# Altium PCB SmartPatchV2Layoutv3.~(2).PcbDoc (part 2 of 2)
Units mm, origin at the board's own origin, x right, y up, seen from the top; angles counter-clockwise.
Board outline 99.82 x 98.31 mm, 4 copper layers (Top Layer, Power, GroundPlane, Bottom Layer), stack 2.286 mm thick; 142 components, 77 nets, 387 pads, 123 vias.
Unrouted connection lines stored in the file: 2.
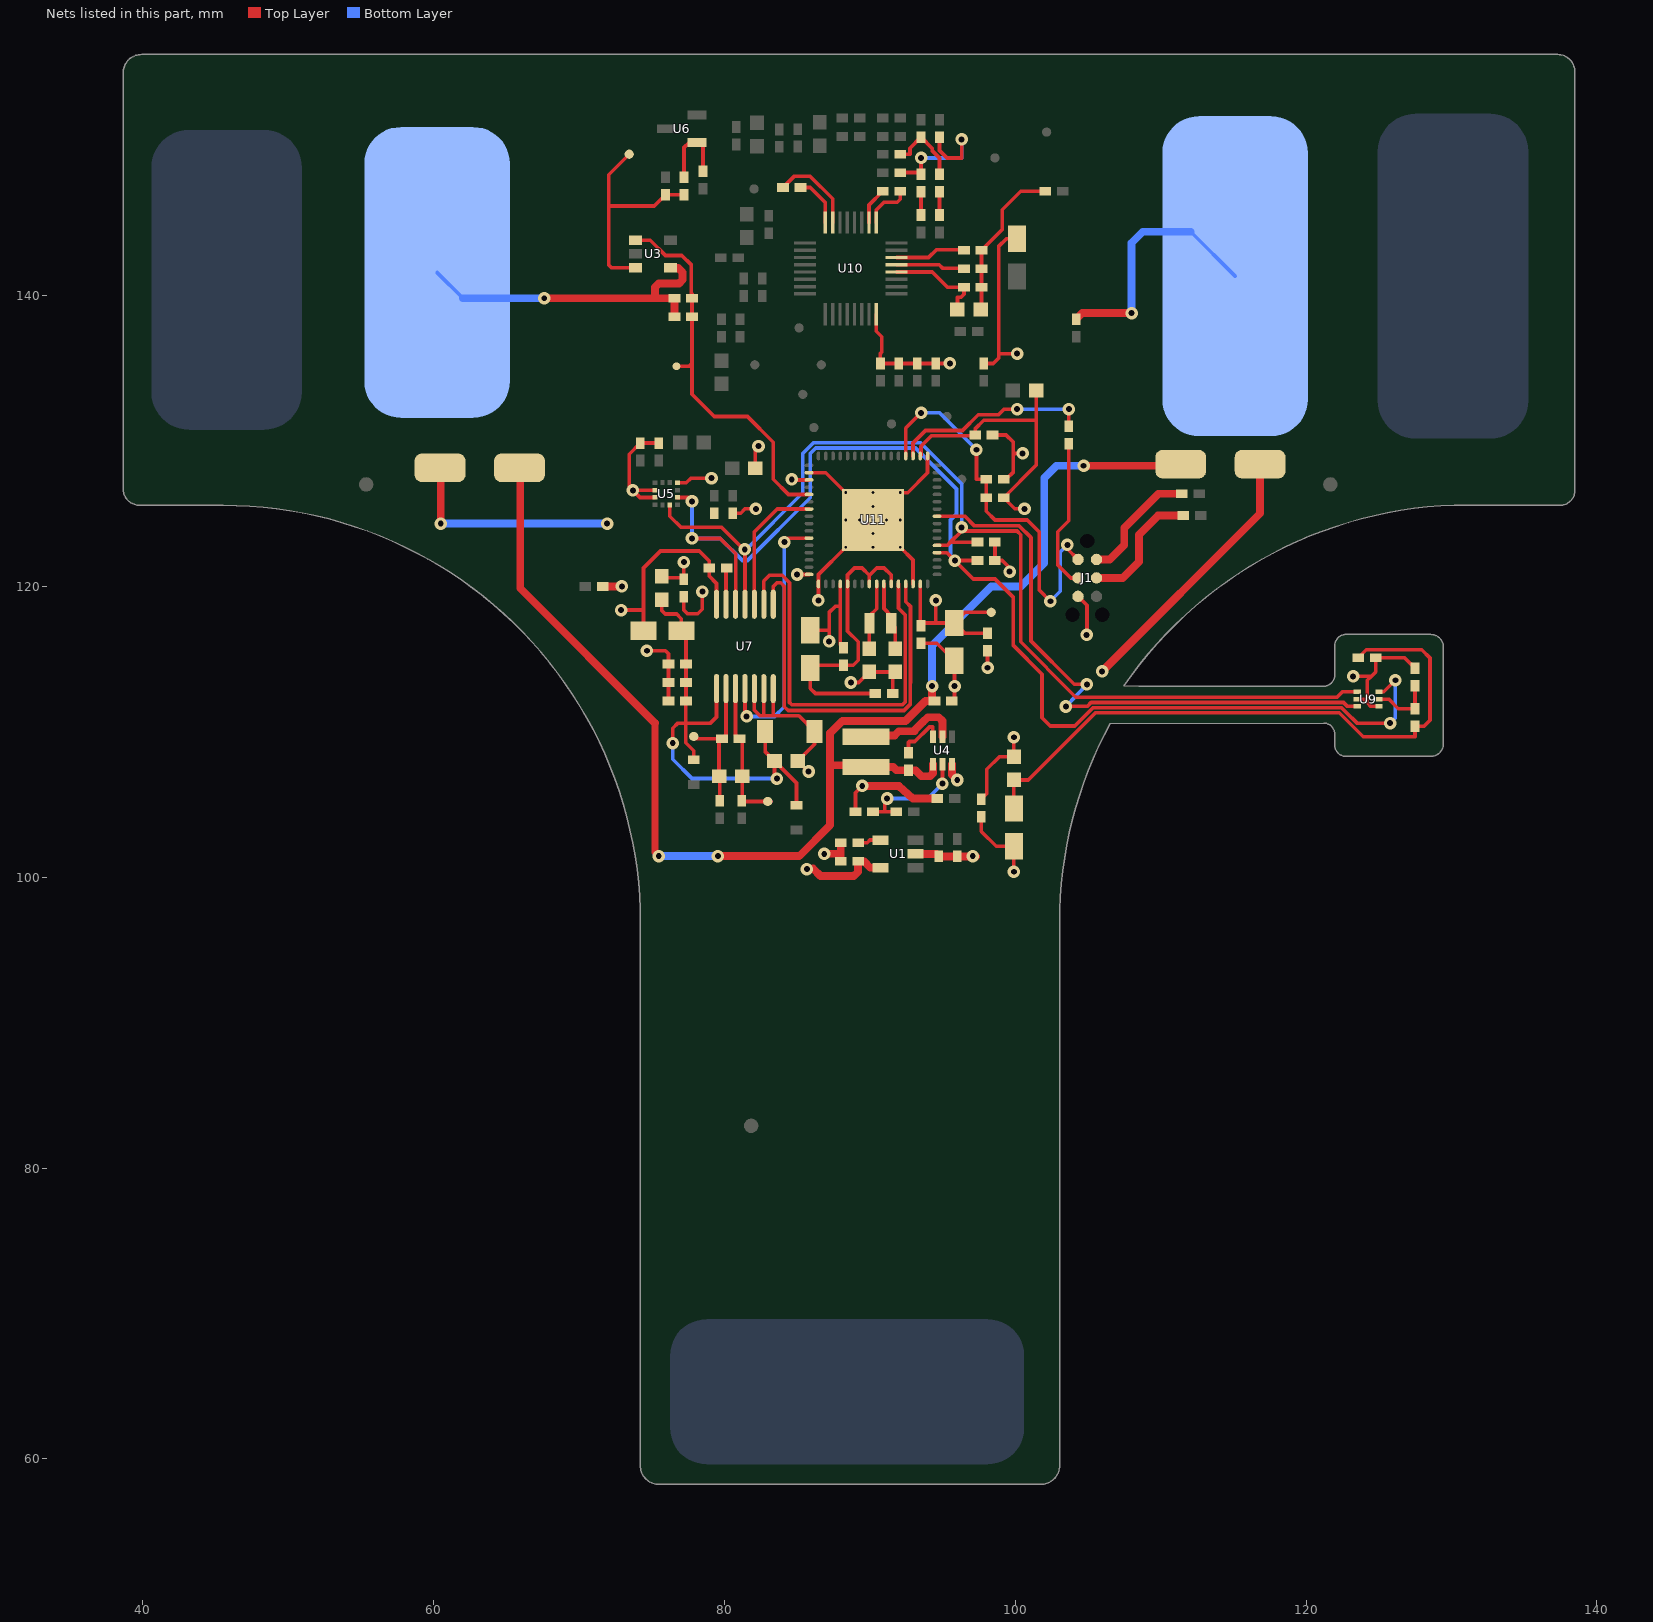
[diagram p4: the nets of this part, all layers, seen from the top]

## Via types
v1: diameter 0.864, hole 0.406, Top Layer to Bottom Layer, 110 vias
v2: diameter 0.5, hole 0.2, Top Layer to Bottom Layer, 13 vias

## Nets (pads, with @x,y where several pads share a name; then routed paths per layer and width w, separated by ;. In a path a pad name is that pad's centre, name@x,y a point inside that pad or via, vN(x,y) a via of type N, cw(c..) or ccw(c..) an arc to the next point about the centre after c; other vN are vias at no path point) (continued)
BOOST_INPUT: BT1.1 BT2.1 C43.1 L8.1 R13.1 U4.1 | length 94.4
  Top Layer w0.254: L8.1@89.739,107.681 L8.1@89.748,107.672 ; v1(94.285,113.132) v1@94.447,112.97
  Top Layer w0.5: 75.235,110.592 75.235,101.702 v1(75.489,101.448)
  Top Layer w0.54: BT1.1@65.964,127.991 65.964,119.863 75.235,110.592 ; v1(79.553,101.448) 85.141,101.448 87.274,103.581 87.274,109.906 88.113,110.744 92.456,110.744 93.828,112.116 C43.1@94.447,112.116 ; 87.274,107.696 L8.1@89.739,107.681 ; L8.1@89.738,107.57 91.616,107.57 91.837,107.35 92.283,107.35 ; R13.1@92.659,107.35 93.145,107.35 93.561,106.934 94.132,106.934 94.346,107.148 U4.1@94.346,107.762 ; C43.1@94.285,112.278 v1(94.285,113.132) ; v1(104.699,128.287) BT2.1@111.048,128.287
  Bottom Layer w0.54: v1(75.489,101.448) v1(79.553,101.448) ; v1(94.285,113.132) 94.285,115.926 98.349,119.99 100.381,119.99 101.997,121.606 101.997,127.448 102.836,128.287 v1(104.699,128.287)
DVCC: 6.1 C1.1 C4.1 C6.1 C10.1 C15.1 C26.1 L1.1 L2.1 L5.1 L7.1 R1.1 R6.2 R34.1 R35.1 U1.5 U11.18 U11.35 U11.48 U11.63 | length 52.8
  Top Layer w0.254: L1.1@75.489,120.59 77.067,120.59 C10.1@77.091,120.613 ; C10.1@77.216,120.488 v1(77.216,121.666) ; L5.1@82.131,128.118 82.131,129.426 v1(82.347,129.642) ; v1@84.677,127.312 U11.35@85.821,127.312 ; v1(85.003,120.812) U11.48@85.821,120.812 ; 89.982,100.65 90.038,100.65 ; U11.63@93.472,120.162 93.472,117.339 C6.1@93.523,117.288 ; U11.18@93.472,128.962 93.518,129.008 93.518,129.637 94.237,130.356 97.193,130.356 C26.1@97.241,130.404 97.241,130.82 97.841,131.42 101.397,131.42 ; C6.1@93.715,117.48 C1.1@95.809,117.48 ; 94.542,117.483 v1(94.542,119.027) ; C15.1@97.665,105.35 98.044,105.728 98.044,107.414 98.915,108.286 L2.1@99.906,108.286 v1(99.906,109.621) ; R1.1@98.095,116.78 96.509,116.78 C1.1@95.809,117.48 ; 6.1@98.349,118.212 96.541,118.212 C1.1@95.809,117.48 ; R35.1@98.603,123.038 R34.1@98.603,121.768 99.111,121.768 99.619,121.26 v1(99.619,121.006) ; v1(100.635,125.324) 99.965,125.324 R6.2@99.203,126.086 101.435,128.318 L7.1@101.435,133.452
  Top Layer w0.54: v1(85.674,100.559) v1@86.081,100.559 ; 86.106,100.584 86.614,100.076 88.9,100.076 89.2,100.376 C4.1@89.2,101.092 89.596,101.092 90.038,100.65 U1.5@90.748,100.65
  other v1: 84.633,127.356
EL_GSR1: 5.1 C34.2 R10.1 U3.4 | length 22.6
  Top Layer w0.254: U3.4@76.297,141.9 76.809,141.9
  Top Layer w0.54: v1(67.615,139.802) R10.1@76.575,139.802 C34.2@76.575,138.532 ; 75.235,139.852 75.235,140.564 75.489,140.818 76.875,140.818 77.129,141.072 77.129,141.58 76.809,141.9
  Bottom Layer w0.254: 5.1@60.249,141.58 5.1@62.027,139.802
  Bottom Layer w0.54: 5.1@62.027,139.802 v1(67.615,139.802)
EL_GSR2: 4.1 R9.2 | length 17.5
  Top Layer w0.54: R9.2@104.191,138.37 104.607,138.786 v1(108.001,138.786)
  Bottom Layer w0.254: 4.1@112.065,144.374 4.1@115.113,141.326
  Bottom Layer w0.54: v1(108.001,138.786) 108.001,143.612 108.763,144.374 4.1@112.065,144.374
GND: BT1.2 BT2.2 C1.2 C3.2 C4.2 C5.2 C6.2 C8.2 C9.2 C10.2 C11.2 C12.2 C14.2 C15.2 C19.2 C21.2 C22.2 C26.2 C27.2 C28.2 C29.2 C33.2 C36.2 C37.2 C38.1 C41.2 C42.2 C43.2 C44.2 C45.2 C46.2 C47.2 C50.2 C51.2 C69.2 C70.2 J1.6 R2.1 R3.1 R20.1 U1.2 U4.3 U5.4 U5.8 U5.9 U7.5 U7.6 U7.7 U7.14 U9.2 U9.4 U10.24 U11.17 U11.34 U11.49 U11.62 U11.65 | length 178.4
  Top Layer w0.254: v1(72.898,118.364) 74.443,118.364 ; C9.2@74.443,116.942 74.443,118.364 ; v1(74.676,115.57) 75.946,115.57 76.159,115.357 C36.2@76.159,114.656 C11.2@76.159,113.386 C37.2@76.159,112.116 ; U5.9@75.222,126.111 74.194,126.111 v1(73.711,126.594) ; U5.8@75.222,126.611 73.728,126.611 v1(73.711,126.594) ; C46.2@75.489,129.847 C21.2@74.219,129.847 73.457,129.085 73.457,126.848 v1(73.711,126.594) ; U5.4@76.772,127.111 77.376,127.111 77.698,127.433 v1(79.117,127.433) ; C10.2@77.216,119.288 77.216,118.364 77.47,118.11 78.174,118.11 78.486,118.422 v1(78.486,119.634) ; U7.14@79.464,118.764 79.464,120.193 78.953,120.704 C38.1@78.953,121.26 78.953,121.745 78.27,122.428 75.611,122.428 74.443,121.26 74.443,118.364 ; C22.2@80.569,125.024 81.124,125.024 81.424,125.324 v1(82.169,125.324) ; U7.5@82.064,112.964 82.064,111.484 82.448,111.1 83.363,111.1 ; 82.714,111.137 U7.6@82.714,112.964 ; U7.7@83.364,112.964 83.363,111.1 ; v1(85.797,107.266) 85.772,107.266 C42.2@85.047,107.991 86.201,109.145 C41.2@86.201,110.023 85.124,111.1 83.363,111.1 ; U11.34@85.821,127.812 86.971,127.812 v2(88.346,126.437) v2(90.221,124.562) ; v1(86.47,119.033) U11.49@86.47,120.162 86.47,120.811 v2(88.346,122.687) v2(90.221,124.562) ; v1(86.868,101.6) v1@86.881,101.613 ; v1(88.697,113.386) 89.243,113.386 C70.2@89.967,114.11 C69.2@91.745,114.11 ; R20.1@89.021,104.496 89.021,105.812 v1(89.483,106.274) ; U10.24@90.447,138.704 90.447,137.544 90.829,137.162 90.829,136.099 90.729,135.999 C51.2@90.729,135.322 C50.2@91.999,135.322 C27.2@93.269,135.322 C28.2@94.539,135.322 v1@95.444,135.322 ; R2.1@91.583,112.624 C69.2@91.583,113.948 ; U11.62@92.971,120.162 92.971,121.811 v2(92.096,122.687) v2(90.221,124.562) ; C6.2@93.523,115.888 C6.2@93.523,116.088 94.601,116.088 C1.2@95.809,114.88 95.827,114.861 v1(95.827,113.132) 95.827,112.296 C43.2@95.647,112.116 C43.2@95.809,111.954 ; U11.17@93.972,128.962 93.972,127.805 92.604,126.437 v2(92.096,126.437) v2(90.221,124.562) ; C5.2@94.574,101.6 C5.2@94.747,101.428 ; v1(97.079,101.448) 97.079,101.194 v1@97.313,101.428 ; C15.2@97.665,104.15 97.665,103.147 98.691,102.122 C12.2@99.906,102.122 v1(99.906,100.374) ; C29.2@97.841,135.322 98.492,135.322 98.857,135.687 98.857,143.358 99.395,143.896 C19.2@100.127,143.896 C19.2@100.127,144.374 ; C26.2@98.441,130.404 99.365,130.404 99.873,129.896 99.873,129.134 ; 98.857,135.992 v1(100.127,135.992) ; C33.2@99.203,127.356 99.365,127.356 99.873,127.864 99.873,129.134 ; v1(100.508,129.134) 99.873,129.134 ; J1.6@104.318,119.304 104.927,118.694 104.927,116.688 v1(104.902,116.662) ; BT2.2@116.586,128.397 BT2.2@116.84,128.143 ; v1(123.228,113.805) 124.473,113.805 ; U9.2@123.507,112.243 123.952,112.243 124.202,111.993 ; U9.4@125.007,111.743 124.452,111.743 124.202,111.993 ; C47.2@127.485,114.373 126.769,115.089 C14.2@124.783,115.089 124.783,114.115 124.473,113.805 ; 124.202,111.993 124.202,113.534 124.473,113.805
  Top Layer w0.54: v1(60.503,124.308) BT1.2@60.503,127.991 ; R3.1@71.646,119.99 v1(72.949,119.99) ; v1@86.881,101.613 88,101.613 ; C4.2@88,101.092 88,101.613 ; C8.2@88,102.362 88,101.613 ; v1(89.483,106.274) 90.799,106.274 91.999,106.274 92.964,105.41 C44.2@94.7,105.41 ; U1.2@93.148,101.6 C5.2@94.574,101.6 ; C5.2@94.747,101.428 C3.2@96.017,101.428 v1@97.313,101.428 ; U4.3@95.646,107.762 95.646,107.046 v1(96.012,106.68) ; v1(105.969,114.148) 116.84,125.019 BT2.2@116.84,128.143
  Bottom Layer w0.54: v1(60.503,124.308) v1(71.933,124.308)
  other v1: 95.504,135.322
  other v2: 90.221,122.687 90.221,123.624 88.346,124.562 89.283,124.562 91.158,124.562 92.096,124.562 90.221,125.499 90.221,126.437
GSR_ANALOG_OUTPUT: 7.1 C34.1 R10.2 U3.1 U11.37 | length 26.9
  Top Layer w0.254: U3.1@73.897,143.8 74.903,143.8 75.955,142.748 77.072,142.748 77.733,142.088 77.733,140.14 77.775,140.098 R10.2@77.775,139.802 C34.1@77.775,138.532 77.775,135.23 ; 7.1@76.708,135.128 77.673,135.128 ; 77.673,135.23 77.775,135.23 ; U11.37@85.821,126.312 84.407,126.312 83.363,127.356 83.363,129.896 81.585,131.674 79.299,131.674 77.775,133.198 77.775,135.23
JTAG_TCK: J1.4 R7.1 | length 10.4
  Top Layer w0.254: R7.1@103.683,129.804 103.683,124.511 102.921,123.749 102.921,121.463 103.81,120.574 J1.4@104.318,120.574
JTAG_TDO/TDI: C33.1 J1.2 R6.1 U11.20 | length 28.1
  Top Layer w0.254: U11.20@92.471,128.962 92.471,130.876 v1(93.523,131.928) ; v1(97.333,129.388) 97.333,127.356 C33.1@98.003,127.356 R6.1@98.003,126.086 98.003,125.162 98.603,124.562 100.829,124.562 101.651,123.74 101.651,119.736 v1(102.413,118.974) ; v1(103.581,122.843) 103.581,122.58 J1.2@104.318,121.844
  Bottom Layer w0.254: v1(93.523,131.928) 94.793,131.928 v1(97.333,129.388) ; v1(102.413,118.974) 103.099,119.659 103.099,122.36 v1(103.581,122.843)
JTAG_TEST/SBWTCK: R7.2 U11.19 | length 13.7
  Top Layer w0.254: U11.19@92.971,128.962 92.971,129.852 93.829,130.71 96.369,130.71 97.46,131.801 98.855,131.801 99.236,132.182 v1(100.127,132.182) ; R7.2@103.683,131.004 v1(103.683,132.182)
  Bottom Layer w0.254: v1(100.127,132.182) v1(103.683,132.182)
JTAG_VCC_TARGET_IN: J1.3 R5.1 | length 8.8
  Top Layer w0.54: J1.3@105.588,120.574 107.391,120.574 108.509,121.691 108.509,122.707 108.509,123.546 109.824,124.861 R5.1@111.56,124.861
JTAG_VCC_TOOL_OUT: J1.1 R4.1 | length 8.4
  Top Layer w0.54: J1.1@105.588,121.844 106.502,121.844 107.493,122.834 107.493,124.003 109.855,126.365 R4.1@111.439,126.365
MSP_AVCC: C2.1 C7.1 R1.2 U11.52 | length 9.3
  Top Layer w0.254: C2.1@86.222,116.972 87.203,116.972 ; v1(87.203,116.21) 87.203,116.972 ; C7.1@87.97,115.982 87.97,118.618 ; U11.52@87.97,120.162 87.97,118.618 ; v1(98.095,114.402) R1.2@98.095,115.58 ; 87.203,116.972 87.203,118.191 87.63,118.618 87.97,118.618
MSP_AVSS: C2.2 C7.2 R2.2 U11.53 U11.56 U11.59 | length 20.5
  Top Layer w0.254: C2.2@85.903,114.372 85.903,112.979 86.258,112.624 R2.2@90.383,112.624 ; C2.2@86.095,114.564 C7.2@88.189,114.564 88.859,114.564 89.205,114.91 89.205,116.18 88.47,116.914 U11.53@88.47,120.162 88.47,120.779 88.951,121.26 89.459,121.26 89.963,120.756 ; U11.56@89.971,120.162 89.971,120.756 90.475,121.26 90.983,121.26 91.471,120.771 U11.59@91.471,120.162
MSP_LFXIN: C70.1 U11.57 Y1.1 | length 4.1
  Top Layer w0.254: C70.1@89.967,115.71 89.967,117.438 Y1.1@89.979,117.45 ; Y1.1@89.979,117.97 90.471,118.462 U11.57@90.471,120.162
MSP_LFXOUT: C69.1 U11.58 Y1.2 | length 4.3
  Top Layer w0.254: U11.58@90.971,120.162 90.971,118.477 Y1.2@91.479,117.97 ; Y1.2@91.479,117.45 91.745,117.184 C69.1@91.745,115.71
MSP_P1.0_INT: U7.10 U11.39 | length 9.4
  Top Layer w0.254: U7.10@82.064,118.764 82.064,123.749 ; 82.079,123.749 83.642,125.312 U11.39@85.821,125.312
MSP_P2.7_INT: U9.3 U11.9 | length 41.6
  Top Layer w0.254: U11.9@94.621,124.812 96.544,124.812 97.202,124.154 100.281,124.154 101.089,123.346 101.089,116.234 104.064,113.259 v1(104.927,113.259) ; v1@103.488,111.743 104.949,111.743 105.217,112.011 122.569,112.011 122.837,111.743 U9.3@123.507,111.743
  Bottom Layer w0.254: v1(103.48,111.735) v1(104.927,113.259)
MSP_P4.0_INT: U7.9 U11.60 | length 28.4
  Top Layer w0.254: U7.9@82.714,118.764 82.714,120.356 83.109,120.752 83.976,120.752 84.479,120.248 84.479,112.016 84.633,111.862 92.253,111.862 92.437,112.046 92.437,113.506 92.447,113.516 92.447,114.704 92.437,114.713 92.437,115.106 92.447,115.116 92.447,116.304 92.437,116.313 92.437,118.027 91.971,118.493 U11.60@91.971,120.162
MSP_P4.1_INT: U7.8 U11.61 | length 27.8
  Top Layer w0.254: U7.8@83.364,118.764 83.364,119.99 83.617,120.244 83.871,120.244 84.125,119.99 84.125,111.718 84.389,111.454 92.353,111.454 ; 92.353,111.461 92.791,111.9 92.791,113.36 92.801,113.369 92.801,118.612 92.471,118.942 U11.61@92.471,120.162
MSP_P9.3_OUT: U7.4 U11.43 | length 18
  Top Layer w0.254: U7.4@81.414,112.964 81.414,111.169 v1(81.534,111.049) ; v1(84.125,123.038) 84.399,123.312 U11.43@85.821,123.312
  Bottom Layer w0.254: v1(81.534,111.049) 83.456,111.049 84.125,111.718 v1(84.125,123.038)
MSP_UCB0SCL_TMP103_SCL_RF430CL330HCPW_SCL: R35.2 U5.12 U7.11 U9.1 U11.5 | length 74.8
  Top Layer w0.254: U5.12@76.247,125.586 76.247,124.82 77.013,124.054 79.807,124.054 v1@81.363,122.497 ; U7.11@81.414,118.764 v1@81.414,122.447 ; U11.5@94.621,122.812 95.329,122.812 95.555,123.038 ; v1(96.317,124.054) v1@96.317,123.8 ; R35.2@97.241,123.038 95.555,123.038 ; U9.1@123.507,112.743 122.496,112.743 122.118,112.365 104.171,112.365 103.988,112.547 100.381,116.18 100.381,123.546 100.127,123.8 v1@96.317,123.8 ; 95.555,123.038 v1@96.317,123.8
  Bottom Layer w0.254: v1(81.405,122.539) 81.414,122.531 81.414,122.447 85.395,126.428 85.395,129.134 86.127,129.866 93.492,129.866 96.317,127.042 v1(96.317,124.054)
MSP_UCB0SDA_TMP103_SDA_RF430CL330HCPW_SDA: R34.2 U5.2 U7.12 U9.6 U11.4 | length 87.6
  Top Layer w0.254: U5.2@76.772,126.111 77.496,126.111 v1(77.775,125.832) ; v1(77.775,123.292) 79.721,123.292 80.78,122.233 80.78,118.78 U7.12@80.764,118.764 ; U11.4@94.621,122.312 95.301,122.312 v1(95.845,121.768) ; R34.2@97.403,121.768 v1(95.845,121.768) ; U9.6@125.007,112.743 125.341,112.743 v1(126.136,113.538) ; v1(125.781,110.592) 123.495,110.592 122.733,111.354 122.725,111.354 122.422,111.657 105.363,111.657 104.095,110.388 102.413,110.388 101.841,110.96 101.841,113.957 99.873,115.926 99.873,119.228 98.603,120.498 97.115,120.498 v1(95.845,121.768)
  Bottom Layer w0.254: v1(77.775,125.832) v1(77.775,123.292) 79.721,123.292 81.245,121.768 81.585,121.768 85.903,126.086 85.903,129.134 86.281,129.512 93.144,129.512 95.963,126.694 95.963,124.97 95.555,124.562 95.555,122.058 v1(95.845,121.768) ; v1(125.781,110.592) 126.136,110.947 v1(126.136,113.538)
Net8_1: 8.1 R11.1 R12.2 U3.3 | length 15.6
  Top Layer w0.254: 72.049,146.152 75.186,146.152 R12.2@75.951,146.917 R11.1@77.221,146.917 ; 8.1@73.457,149.708 72.049,148.3 72.049,142.088 72.237,141.9 U3.3@73.897,141.9
Net9_1: 9.1 C39.1 C40.1 R17.1 U7.2 | length 9.9
  Top Layer w0.254: 9.1@77.897,109.676 78.059,109.515 C40.1@79.837,109.515 ; R17.1@79.675,105.255 79.675,106.903 C39.1@79.637,106.941 79.637,109.315 C40.1@79.837,109.515 ; U7.2@80.114,112.964 80.114,109.791 C40.1@79.837,109.515
Net10_1: 10.1 C39.2 C40.2 R18.1 U7.3 | length 9.9
  Top Layer w0.254: U7.3@80.764,112.964 80.764,109.788 C40.2@81.037,109.515 81.237,109.315 C39.2@81.237,106.941 81.237,105.293 81.334,105.197 10.1@83.231,105.197
NetC8_1: C8.1 U1.4 | length 1.6
  Top Layer w0.254: C8.1@89.2,102.362 89.819,102.362 90.007,102.55 U1.4@90.748,102.55
NetC38_2: C38.2 U7.13 | length 2.5
  Top Layer w0.254: U7.13@80.114,118.764 80.114,121.22 C38.2@80.153,121.26
NetC47_1: C47.1 R21.1 U9.5 | length 4.3
  Top Layer w0.254: U9.5@125.007,112.243 125.679,112.243 126.342,111.579 R21.1@127.485,111.579 C47.1@127.485,113.173
NetC54_1: C54.1 R22.2 R23.2 R24.2 R25.1 | length 10.9
  Top Layer w0.254: C54.1@97.679,139.094 R22.2@97.679,140.564 R24.2@97.679,141.834 97.679,141.876 R23.2@97.679,143.104 99.111,144.536 99.111,145.898 99.831,146.618 100.381,147.168 R25.1@102.067,147.168
NetC54_2: C54.2 R22.1 U10.28 | length 6.9
  Top Layer w0.254: U10.28@91.846,141.603 94.299,141.603 95.339,140.564 R22.1@96.479,140.564 96.479,140.078 96.279,139.878 96.025,139.878 C54.2@96.025,139.04
NetC56_1: C56.1 U10.2 | length 2.6
  Top Layer w0.254: U10.2@89.947,145.003 89.947,146.224 C56.1@90.891,147.168
NetC56_2: C56.2 U10.1 | length 3.4
  Top Layer w0.254: U10.1@90.447,145.003 90.447,145.87 90.983,146.406 91.885,146.406 92.091,146.612 C56.2@92.091,147.168
NetC57_2: C57.2 C59.2 C60.2 | length 10.4
  Top Layer w0.254: C57.2@92.091,148.45 C60.2@93.394,148.45 ; C60.2@93.523,148.322 v1(93.523,149.454) ; C59.2@94.793,150.886 94.798,150.88 94.798,149.967 95.312,149.454 96.317,149.454 v1(96.317,150.724)
  Bottom Layer w0.254: v1(93.523,149.454) 96.317,149.454 v1(96.317,150.724)
NetC58_1: C58.1 U10.8 | length 3.5
  Top Layer w0.254: C58.1@85.233,147.422 85.903,147.422 86.947,146.378 U10.8@86.947,145.003
NetC58_2: C58.2 U10.7 | length 6
  Top Layer w0.254: C58.2@84.033,147.422 84.795,148.184 85.903,148.184 87.447,146.64 U10.7@87.447,145.003
NetC60_1: C60.1 R29.1 | length 1.6
  Top Layer w0.254: R29.1@93.523,145.528 C60.1@93.523,147.122
NetC63_2: C63.2 C64.2 C65.2 | length 5.3
  Top Layer w0.254: C65.2@92.091,149.708 92.761,149.708 92.761,150.124 C63.2@93.523,150.886 94.285,150.124 94.285,149.962 94.793,149.454 C64.2@94.793,148.322
NetC64_1: C64.1 R30.1 | length 1.6
  Top Layer w0.254: R30.1@94.793,145.528 C64.1@94.793,147.122
NetL8_2: L8.2 U4.5 | length 5.5
  Top Layer w0.254: 93.066,110.033 93.066,110.084
  Top Layer w0.54: L8.2@91.186,109.752 91.718,109.752 91.999,110.033 93.066,110.033 ; 93.066,110.084 93.646,110.664 93.98,110.998 94.742,110.998 94.996,110.744 U4.5@94.996,109.662
NetR8_1: R8.1 R11.2 U6.1 | length 5.5
  Top Layer w0.254: R11.2@77.221,148.117 77.221,150.17 77.587,150.536 78.537,150.536 R8.1@78.537,148.53
NetR13_2: R13.2 U4.6 | length 3.5
  Top Layer w0.254: R13.2@92.659,108.55 92.659,109.271 92.71,109.322 93.091,109.322 94.096,110.327 94.336,110.327 94.336,109.672 U4.6@94.346,109.662
NetR19_1: R19.1 R20.2 U4.2 | length 8.1
  Top Layer w0.254: R20.2@90.221,104.496 91.018,104.496 ; v1(91.186,105.41) 91.018,105.242 91.018,104.496 ; R19.1@91.815,104.496 91.018,104.496 ; v1(94.996,106.426) U4.2@94.996,107.762
  Bottom Layer w0.254: v1(91.186,105.41) 93.98,105.41 v1(94.996,106.426)
NetR23_1: R23.1 U10.30 | length 4.9
  Top Layer w0.254: U10.30@91.846,142.603 94.038,142.603 94.581,143.146 R23.1@96.479,143.146
NetR24_1: R24.1 U10.29 | length 4.7
  Top Layer w0.254: U10.29@91.846,142.103 94.777,142.103 95.005,141.876 R24.1@96.479,141.876
RF430_DVCC: C9.1 C11.1 C36.1 C37.1 C41.1 C42.1 D1.1 D2.1 L1.2 U7.1 | length 34
  Top Layer w0.254: 75.692,118.512 75.692,118.338 75.938,118.092 76.726,118.092 77.043,117.775 C9.1@77.043,116.942 C9.1@77.267,117.166 ; v1(76.454,109.22) 76.454,110.236 76.81,110.592 77.353,110.592 ; C37.1@77.359,112.116 C11.1@77.359,113.386 C36.1@77.359,114.656 C9.1@77.359,116.626 ; C37.1@77.451,112.024 77.353,111.926 77.353,110.592 ; D1.1@77.897,108.079 77.897,108.691 77.353,109.235 77.353,110.592 ; U7.1@79.464,112.964 79.464,111.01 79.045,110.592 77.353,110.592 ; C41.1@82.801,110.023 82.801,108.637 C42.1@83.447,107.991 ; v1(83.617,106.782) 83.447,106.951 C42.1@83.447,107.991 ; D2.1@84.963,104.989 84.963,106.475 C42.1@83.447,107.991
  Bottom Layer w0.254: v1(76.454,109.22) 76.454,108.102 77.775,106.782 v1(83.617,106.782)
TMP_DVCC: C12.1 C14.1 L2.2 R21.2 | length 43.8
  Top Layer w0.254: C12.1@99.906,104.722 L2.2@99.906,106.686 100.893,106.686 105.51,111.303 122.276,111.303 123.927,109.652 127.485,109.652 R21.2@127.485,110.379 128.109,110.379 128.519,110.79 128.519,115.071 127.951,115.639 124.133,115.639 C14.1@123.583,115.089
pads on no net: FID1.1 FID2.1 FID3.1 J1.5 J1.MH1 J1.MH2 J1.MH3 U5.10 U6.3 U10.17 U11.1 U11.2 U11.3 U11.6 U11.7 U11.8 U11.10 U11.11 U11.12 U11.13 U11.15 U11.21 U11.22 U11.23 U11.24 U11.36 U11.40 U11.41 U11.42 U11.44 U11.45 U11.46 U11.47 U11.50 U11.51 U11.54 U11.55 U11.64
copper on no net: | length 0.5
  Top Layer w0.254: 104.648,124.206 v1(104.648,124.714)

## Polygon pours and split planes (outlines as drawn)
ADS_DVCC on Power (split plane): 102.537,142.288 102.537,131.727 101.902,131.092 78.794,131.092 78.158,131.727 78.158,133.144 79.352,134.338 93.269,134.338 93.318,134.348 93.36,134.376 98.44,139.456 98.468,139.498 98.478,139.548 98.478,142.796 98.887,143.205 101.621,143.205
MSP_AVCC on Power (split plane): 87.714,117.065 88.059,116.61 88.059,112.624 88.069,112.574 88.097,112.532 88.139,112.504 88.189,112.494 96.155,112.494 96.204,112.504 96.246,112.532 97.17,113.456 97.198,113.498 97.208,113.548 97.208,115.796 98.971,115.796 98.971,115.57 98.971,113.937 98.511,113.477 97.234,112.2 96.771,111.737 86.93,111.737 86.286,112.41 86.286,116.653 86.701,117.089
ADS_AVCC on Power (split plane): 90.853,154.534 90.812,146.998 82.093,147.043 82.068,147.038 82.044,147.033 82.043,147.033 82.023,147.019 82.002,147.006 82.002,147.005 82.001,147.005 81.987,146.984 81.973,146.964 81.973,146.963 81.968,146.939 81.963,146.914 81.963,143.104 81.973,143.054 82.001,143.012 82.043,142.984 82.093,142.974 86.789,142.974 86.789,141.201 83.617,141.201 83.567,141.191 83.525,141.163 83.497,141.121 83.487,141.072 83.487,135.359 77.345,135.359 77.345,139.09 77.336,139.14 77.308,139.182 75.11,141.379 75.11,145.59 78.127,148.607 79.266,148.607 79.291,148.612 79.315,148.616 79.315,148.617 79.316,148.617 79.336,148.631 79.357,148.644 79.357,148.645 79.358,148.645 79.371,148.665 79.385,148.686 79.386,148.687 79.39,148.711 79.395,148.736 79.428,154.658 90.853,154.658
DVCC on Power (split plane): 356 vertices, not listed, extent 39.167,58.766 137.972,156.056
GND on GroundPlane (split plane): 256 vertices, not listed, extent 70.741,58.766 128.932,136.878
ADS_AVSS on GroundPlane (split plane): 172 vertices, not listed, extent 39.167,112.057 137.972,156.056

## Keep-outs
Keep-Out Layer:
  text ".Layer_Name" at 141.224,106.68 h1.52

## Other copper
Top Layer:
  text ".Layer_Name" at 141.224,154.94 h1.52
Bottom Layer:
  text ".Layer_Name" at 141.224,152.4 h1.52
  text "SVN:" at 49.847,114.91 h1.52 r90
  text ".VersionControl_RevNumber" at 49.847,107.823 h1.52 r90
  text "UL94V-0" at 52.21,73.241 h1.52 r90
Power (plane layer: these items are gaps in the copper):
  rectangle: 74.981,69.952 100.381,99.67
  lines w0.254: 99.101,115.57 99.101,115.926 ; 99.101,115.926 98.697,115.926 97.079,115.926 97.079,113.548 96.155,112.624 88.408,112.624 88.189,112.624 88.189,116.654 87.779,117.193 86.647,117.219 86.157,116.705 86.157,112.358 86.875,111.608 92.343,111.608 96.825,111.608 97.325,112.108 98.603,113.386 99.101,113.884 99.101,115.926 ; 74.981,141.326 77.216,139.09 77.216,135.23 81.389,135.23 83.617,135.23 83.617,141.072 86.919,141.072 86.919,143.104 82.093,143.104 82.093,146.914 90.941,146.868 90.983,154.534 90.983,154.788 79.299,154.788 79.266,148.736 78.073,148.736 74.981,145.644 74.981,141.326 ; 78.029,131.674 78.029,133.198 79.299,134.468 93.269,134.468 98.349,139.548 98.349,142.85 98.833,143.334 101.674,143.334 102.667,142.342 102.667,131.674 101.956,130.962 78.74,130.962 78.029,131.674
GroundPlane (plane layer: these items are gaps in the copper):
  rectangle: 74.981,69.952 100.381,99.67
  lines w0.254: 71.046,110.998 70.612,111.432 70.612,111.76 70.612,127.864 77.877,127.864 ; 77.911,127.888 89.581,136.398 96.52,136.398 96.52,135.636 99.111,135.636 99.111,137.008 102.159,137.008 102.159,128.626 107.489,123.296 107.507,113.538

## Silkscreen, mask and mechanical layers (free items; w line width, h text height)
Top Overlay:
  region: 96.52,77.724 96.52,85.344 93.98,85.344 93.98,77.724
  text ".Layer_Name" at 141.224,127 h1.52
  text "Smart Patch V2.0" at 80.264,91.44 h1.02
  text "REV A" at 80.264,89.916 h1.02
  text "TI" at 92.354,87.884 h1.52
  text "©" at 94.996,87.63 h2.67
  text ".CopyrightYear" at 85.344,77.724 h1.52
  text "MADE IN U.S." at 78.994,75.438 h1.52
  text "-" at 51.105,67.666 h1.52 r90
Bottom Overlay:
  text ".Layer_Name" at 141.224,124.46 h1.52
Top Paste:
  text ".Layer_Name" at 141.224,121.92 h1.52
Bottom Paste:
  text ".Layer_Name" at 141.224,119.38 h1.52
Top Solder:
  text ".Layer_Name" at 141.224,116.84 h1.52
  text ".Layer_Name" at 141.224,114.3 h1.52
Bottom Solder:
  text ".Layer_Name" at 141.224,111.76 h1.52
Drill Guide:
  text ".Layer_Name" at 141.224,109.22 h1.52
M1 Board Outline:
  lines w0.254: 38.657,126.714 ccw(c39.804,126.714) 39.804,125.568 45.537,125.568 cw(c45.537,96.876) 74.229,96.876 ; 38.659,126.714 38.659,155.296 cw(c39.929,155.296) 39.929,156.566 137.294,156.566 cw(c137.294,155.379) 138.481,155.379 138.481,126.594 cw(c137.454,126.594) 137.454,125.567 132.639,125.576 131.115,125.588 ccw(c131.115,96.896) 107.469,113.147 108.509,113.132 121.209,113.132 ccw(c121.209,113.894) 121.971,113.894 121.971,115.926 cw(c122.733,115.926) 122.733,116.688 128.575,116.688 cw(c128.575,115.82) 129.442,115.82 129.442,109.173 cw(c128.575,109.173) 128.575,108.306 122.733,108.306 cw(c122.733,109.068) 121.971,109.068 121.971,109.576 121.971,109.83 ccw(c121.209,109.83) 121.209,110.592 106.525,110.565 ccw(c131.74,96.875) 103.048,96.875 103.048,59.538 ; 74.219,59.527 ccw(c75.489,59.527) 75.489,58.257 101.778,58.257 ccw(c101.778,59.527) 103.048,59.527 ; 74.219,59.538 74.219,96.875
  text ".Layer_Name" at 141.224,149.86 h1.52
M2 Board Dimensions:
  rectangle: 17.577,32.982 20.752,36.157
  rectangle: 20.752,29.807 30.277,32.982
  lines w0.178: 17.577,32.982 42.977,32.982 ; 20.752,29.807 20.752,36.157 ; 23.927,29.807 23.927,36.157 ; 30.277,29.807 30.277,36.157 ; 36.627,29.807 36.627,36.157 ; 17.577,29.807 42.977,29.807 42.977,36.157 17.577,36.157 17.577,29.807
  text ".Layer_Name" at 18.034,37.338 h1.52
M3 3D STEP Top:
  text ".Layer_Name" at 141.224,147.32 h1.52
M4 3D STEP Bottom:
  text ".Layer_Name" at 141.224,144.78 h1.52
M5 Assembly Top:
  lines w0.254: 10.16,16.607 177.8,16.607 ; 10.16,21.772 177.851,21.772 ; 10.16,26.937 10.16,11.443 111.887,11.443 177.851,11.443 177.851,26.937 10.173,26.937 10.173,11.443 50.19,11.443 ; 72.771,11.443 72.771,26.937 ; 104.953,21.772 104.953,26.937 ; 126.289,21.772 126.289,26.937 ; 142.088,11.278 142.088,16.43
  text "COMPONENTS MARKED 'DNP' SHOULD NOT BE POPULATED." at 46.876,32.144 h1.52
  text "ASSEMBLY VARIANT:" at 46.863,29.21 h1.52
  text ".VariantName" at 73.177,29.21 h1.52
  text "PCB VIEWED FROM TOP SIDE" at 11.773,23.58 h1.52
  text "BOARD #:" at 74.676,23.58 h1.52
  text ".PRJ_Number" at 88.532,23.58 h1.52
  text "REV:" at 109.982,23.58 h1.52
  text ".PCB_Rev" at 117.386,23.58 h1.52
  text "SVN REV:" at 131.267,23.58 h1.52
  text ".VersionControl_RevNumber" at 144.12,23.58 h1.52
  text "IGNORE ->" at 11.773,18.428 h1.52
  text "PLOT NAME =" at 11.773,13.199 h1.52
  text ".plot_File_Name" at 32.233,13.199 h1.52
  text "GENERATED    :" at 74.727,13.199 h1.52
  text ".Print_Date" at 96.812,13.199 h1.52
  text ".Print_Time" at 115.329,13.199 h1.52
  text "TEXAS INSTRUMENTS" at 147.447,13.199 h1.52
M6 Assembly Bottom:
  lines w0.254: 10.147,21.759 177.838,21.759 ; 10.198,16.595 177.838,16.595 ; 45.91,11.265 45.91,16.417 ; 61.709,21.759 61.709,26.924 ; 83.045,21.759 83.045,26.924 ; 115.227,11.43 115.227,26.924 ; 137.808,11.43 177.825,11.43 177.825,26.924 10.147,26.924 10.147,11.43 76.111,11.43 177.838,11.43 177.838,26.924
  text "COMPONENTS MARKED 'DNP' SHOULD NOT BE POPULATED." at 172.568,32.156 h1.52
  text ".VariantName" at 146.05,29.21 h1.52
  text "ASSEMBLY VARIANT:" at 172.441,29.21 h1.52
  text ".VersionControl_RevNumber" at 43.878,23.567 h1.52
  text "SVN REV:" at 56.731,23.567 h1.52
  text ".PCB_Rev" at 70.612,23.567 h1.52
  text "REV:" at 78.016,23.567 h1.52
  text ".PRJ_Number" at 99.466,23.567 h1.52
  text "BOARD #:" at 113.322,23.567 h1.52
  text "PCB VIEWED FROM BOTTOM SIDE" at 176.225,23.567 h1.52
  text "IGNORE ->" at 82.292,18.428 h1.52
  text "TEXAS INSTRUMENTS" at 40.551,13.187 h1.52
  text ".Print_Time" at 72.669,13.187 h1.52
  text ".Print_Date" at 91.186,13.187 h1.52
  text "GENERATED    :" at 113.271,13.187 h1.52
  text ".plot_File_Name" at 155.766,13.187 h1.52
  text "PLOT NAME =" at 176.225,13.187 h1.52
M9 Title Sheet:
  drawing of 57 lines, arcs and shapes, not listed
  text "1" at 36.369,243.091 h1.78
  text "2" at 99.758,243.091 h1.78
  text "3" at 162.988,243.091 h1.78
  text "4" at 226.657,243.091 h1.78
  text "5" at 290.131,243.091 h1.78
  text "6" at 353.758,243.091 h1.78
  text "A" at 6.998,214.058 h1.78
  text "A" at 382.918,214.058 h1.78
  text "B" at 6.998,153.606 h1.78
  text "B" at 382.918,153.606 h1.78
  text ".Layer_Name" at 141.224,142.24 h1.52
  text "C" at 6.998,93.281 h1.78
  text "C" at 382.918,93.281 h1.78
  text "PROJECT TITLE:" at 305.702,46.012 h1.14
  text ".PRJ_Title" at 306.972,42.626 h1.78
  text "DESIGNED FOR:" at 305.702,38.367 h1.14
  text ".PRJ_Customer" at 306.972,34.811 h1.78
  text "D" at 6.998,33.084 h1.78
  text "D" at 382.918,33.084 h1.78
  text "FILE NAME:" at 305.702,30.747 h1.14
  text ".PCB_File_Name_No_Path" at 306.972,27.699 h1.78
  text "Texas Instruments (TI) and/or its licensors do not warrant the accuracy or completeness of this specification" at 179.476,23.588 h1.14
  text "ENGINEER:" at 305.702,23.381 h1.14
  text "LAYOUT BY:" at 343.929,23.381 h1.14
  text "or any information contained therein. TI and/or its licensors do not warrant that this design will meet" at 178.334,20.726 h1.14
  text ".PRJ_Engineer" at 306.972,19.444 h1.78
  text ".PCB_Layout" at 345.211,19.444 h1.78
  text "the specifications, will be suitable for your application or fit for any particular purpose, or will operate in" at 178.334,17.865 h1.14
  text "ALTIUM DESIGNER VERSION:" at 343.929,15.507 h1.14
  text "an implementation. TI and/or its licensors do not warrant that the design is production worthy. You should" at 178.334,15.003 h1.14
  text "completely validate and test your design implementation to confirm the system functionality for your application." at 179.476,12.141 h1.14
  text ".print_Scale" at 306.972,12.12 h1.78
  text ".Application_BuildNumber" at 345.211,12.12 h1.78
  text "1" at 36.369,6.871 h1.78
  text "2" at 99.758,6.871 h1.78
  text "3" at 162.988,6.871 h1.78
  text "4" at 226.657,6.871 h1.78
  text "5" at 290.131,6.871 h1.78
  text "6" at 353.758,6.871 h1.78
M10 Fab Notes:
  drawing of 185 lines, arcs and shapes, not listed
  text "DESIGN INFORMATION" at 332.055,190.348 h1.52
  text "MIN. TRACK WIDTH:" at 315.683,185.776 h1.52
  text "8" at 343.527,185.776 h1.52
  text "MIL" at 347.458,185.776 h1.52
  text "MIN. CLEARANCE:" at 315.683,182.423 h1.52
  text "0.2" at 342.003,182.423 h1.52
  text "mm" at 347.458,182.423 h1.52
  text "MIN. VIA PAD SIZE:" at 315.683,179.07 h1.52
  text "24" at 342.766,179.07 h1.52
  text "MIL" at 347.458,179.07 h1.52
  text "0.05mm (2MIL)" at 333.336,175.471 h1.52
  text "MINIMUM ANNULAR RING" at 307.32,175.362 h1.52
  text "EXTERNAL" at 351.319,175.362 h1.52
  text "PER" at 312.4,172.364 h1.52
  text "IPC-D-275 CLASS 2 LEVEL C" at 317.988,172.364 h1.52
  text "MIL, HOLES" at 355.789,169.512 h1.52
  text "+/-" at 345.821,169.494 h1.52
  text "+/-" at 367.513,169.494 h1.52
  text "REGISTRATION TOLERANCES:" at 307.32,169.367 h1.52
  text "METAL" at 337.795,169.367 h1.52
  text "5" at 352.43,169.367 h1.52
  text "3" at 373.588,169.367 h1.52
  text "MIL" at 376.541,169.367 h1.52
  text "MATERIAL:" at 305.421,164.047 h1.52
  text "FR-4 High Tg" at 330.477,160.482 h1.52
  text "FR-408" at 316.115,160.265 h1.52
  text "X" at 326.579,160.265 h1.52
  text "OTHER" at 353.91,160.265 h1.52
  text "62 MIL (1.6mm) +/-10%" at 324.245,156.132 h1.52
  text "THICKNESS:" at 307.32,156.023 h1.52
  text "X" at 320.99,156.023 h1.52
  text "OTHER" at 356.882,156.023 h1.52
  text "TOLERANCE:" at 307.32,152.01 h1.52
  text "X" at 328.639,152.01 h1.52
  text "ANSI IPC-6012 TYPE 3 CLASS 2" at 333.387,152.01 h1.52
  text "OTHER +/-" at 333.387,148.047 h1.52
  text "BOW & TWIST:" at 307.32,144.06 h1.52
  text "X" at 328.639,144.06 h1.52
  text "ANSI IPC-6012 TYPE 3 CLASS 2" at 333.387,144.06 h1.52
  text "OTHER +/-" at 333.387,140.034 h1.52
  text ".Layer_Name" at 141.224,139.7 h1.52
  text "DRILLING:" at 305.421,136.516 h1.52
  text "REFERENCE:" at 307.32,133.544 h1.52
  text "X" at 323.785,133.544 h1.52
  text "AS SHOWN" at 328.535,133.544 h1.52
  text "X" at 346.671,133.544 h1.52
  text "NC_DRILL FILES" at 350.151,133.544 h1.52
  text "PTH MIN COPPER THICKNESS:" at 307.32,129.531 h1.52
  text "X" at 341.616,129.531 h1.52
  text "1MIL" at 345.096,129.531 h1.52
  text "OTHER" at 357.72,129.531 h1.52
  text "BOARD FINISH:" at 305.421,125.492 h1.52
  text "SILKSCREEN:" at 309.364,122.495 h1.52
  text "X" at 333.463,122.495 h1.52
  text "TOP" at 336.663,122.495 h1.52
  text "X" at 346.417,122.495 h1.52
  text "BOTTOM" at 349.643,122.495 h1.52
  text "SILKSCREEN COLOR:" at 310.634,118.26 h1.52
  text "X" at 333.436,118.253 h1.52
  text "WHITE" at 336.663,118.253 h1.52
  text "OTHER" at 349.643,118.253 h1.52
  text "SOLDER RESIST COLOR:" at 309.364,113.935 h1.52
  text "GREEN" at 327.011,109.892 h1.52
  text "BLUE" at 342.023,109.892 h1.52
  text "OTHER" at 355.688,109.892 h1.52
  text "X" at 323.785,109.644 h1.52
  text "IMMERSION GOLD (ENIG)" at 332.371,105.103 h1.52
  text "ENEPIG" at 366.344,105.02 h1.52
  text "SURFACE FINISH:" at 305.421,104.994 h1.52
  text "X" at 327.622,104.994 h1.52
  text "IMM. TIN/SILVER OR EQUIV" at 313.792,101.007 h1.52
  text "OTHER" at 350.151,101.007 h1.52
  text "ARRAY/PANEL:" at 305.421,96.46 h1.52
  text "CUT AND TRIM PER MECH LAYER 1" at 332.371,96.351 h1.52
  text "N.C. ROUTE" at 332.371,92.498 h1.52
  text "X" at 349.617,92.498 h1.52
  text "V. SCORE" at 354.367,92.498 h1.52
  text "CERTIFICATION:" at 305.421,89.018 h1.52
  text "MATERIALS AND WORKMANSHIP FOR ALL PCBS" at 323.836,89.018 h1.52
  text "TO MEET OR EXCEED THE REQUIREMENTS OF:" at 323.836,86.529 h1.52
  text "X" at 314.349,83.061 h1.52
  text "ANSI IPC-A-600F CLASS ->" at 317.88,83.061 h1.52
  text "X" at 359.512,83.061 h1.52
  text "2" at 362.533,83.061 h1.52
  text "1" at 354.532,83.023 h1.52
  text "3" at 371.525,83.023 h1.52
  text "X" at 314.402,79.01 h1.52
  text "UL 94V-0" at 317.88,79.01 h1.52
  text "X" at 335.026,79.01 h1.52
  text "RoHS" at 338.505,79.01 h1.52
  text "OTHER" at 354.873,79.01 h1.52
  text "PER ORDER" at 364.958,79.01 h1.52
  text "ADDITIONAL REQUIREMENTS:" at 305.193,75.302 h1.52
  text "MICROSECTION:" at 307.092,72.381 h1.52
  text "YES" at 330.098,72.381 h1.52
  text "REQUIRED" at 352.208,68.542 h1.52
  text "NONE" at 340.486,68.469 h1.52
  text "X" at 348.982,68.469 h1.52
  text "PER ORDER" at 367.245,68.469 h1.52
  text "BARE BOARD ELEC. TEST:" at 307.092,68.342 h1.52
  text "MANUFACTURER'S UL:" at 307.092,64.354 h1.52
  text "METAL" at 349.422,64.373 h1.52
  text "X" at 358.953,64.364 h1.52
  text "SILK" at 362.419,64.373 h1.52
  text "RAIL" at 336.702,64.245 h1.52
M11 Gerber Information:
  lines w0.254: 10.16,16.607 177.8,16.607 ; 10.16,21.772 177.851,21.772 ; 10.16,26.937 10.16,11.443 111.887,11.443 177.851,11.443 177.851,26.937 10.173,26.937 10.173,11.443 50.19,11.443 ; 72.771,11.443 72.771,26.937 ; 104.953,21.772 104.953,26.937 ; 126.289,21.772 126.289,26.937 ; 142.088,11.278 142.088,16.43
  text "ALL ARTWORK VIEWED FROM TOP SIDE" at 11.773,23.58 h1.52
  text "BOARD #:" at 74.676,23.58 h1.52
  text ".PRJ_Number" at 88.532,23.58 h1.52
  text "REV:" at 109.982,23.58 h1.52
  text ".PCB_Rev" at 117.386,23.58 h1.52
  text "SVN REV:" at 131.267,23.58 h1.52
  text ".VersionControl_RevNumber" at 144.12,23.58 h1.52
  text "LAYER NAME =" at 11.773,18.428 h1.52
  text "PLOT NAME =" at 11.773,13.199 h1.52
  text ".plot_File_Name" at 32.233,13.199 h1.52
  text "GENERATED    :" at 74.727,13.199 h1.52
  text ".Print_Date" at 96.812,13.199 h1.52
  text ".Print_Time" at 115.329,13.199 h1.52
  text "TEXAS INSTRUMENTS" at 147.447,13.199 h1.52
M12 Stackup:
  lines w0.152: 305.105,221.59 369.875,221.59 ; 305.105,224.241 369.875,224.241 ; 303.581,209.271 ccw(c304.444,209.271) 304.444,208.407 370.535,208.407 ccw(c370.535,209.271) 371.399,209.271 371.399,227.203 ccw(c370.535,227.203) 370.535,228.067 304.444,228.067 ccw(c304.444,227.203) 303.581,227.203 303.581,209.271
  text "The Stackup Legend below this is static." at 311.34,232.118 h1.52
  text "If you change the stackup, update the Legend." at 311.594,229.832 h1.52
  text "Layer Stack Up Detail for: Ref_Design.PcbDoc" at 305.105,225.072 h1.45
  text "Layer" at 305.105,223.251 h0.61
  text "Gerber" at 327.858,223.251 h0.61
  text "Copper" at 342.172,223.251 h0.61
  text "Dielectric" at 357.481,223.251 h0.61
  text "Name" at 305.105,222.032 h0.61
  text "Document" at 327.858,222.032 h0.61
  text "Thickness" at 342.172,222.032 h0.61
  text "Material" at 357.481,222.032 h0.61
  text "Top Solder Mask" at 305.105,219.67 h0.86
  text "(.GTS)" at 327.858,219.67 h0.86
  text "Solder Resist" at 357.481,219.67 h0.86
  text ".Layer_Name" at 284.988,218.186 h1.52
  text "Top Layer" at 305.105,217.213 h0.86
  text "(.GTL)" at 327.858,217.213 h0.86
  text "1.4mil" at 342.172,217.213 h0.86
  text "FR-4" at 357.481,215.984 h0.86
  text "Bottom Layer" at 305.105,214.755 h0.86
  text "(.GBL)" at 327.858,214.755 h0.86
  text "1.4mil" at 342.172,214.755 h0.86
  text "Bottom Solder Mask" at 305.105,212.298 h0.86
  text "(.GBS)" at 327.858,212.298 h0.86
  text "Solder Resist" at 357.481,212.298 h0.86
M13 Component Bodies Top:
  text ".Layer_Name" at 141.224,137.16 h1.52
M14 Component Bodies Bottom:
  text ".Layer_Name" at 141.224,134.62 h1.52
M15 Courtyards Top:
  text ".Layer_Name" at 141.224,132.08 h1.52
M16 Courtyards Bottom:
  text ".Layer_Name" at 141.224,129.54 h1.52
Drill Drawing:
  text ".Layer_Name" at 141.224,104.14 h1.52

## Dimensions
38.659,155.296 to 138.481,155.379 on M2 Board Dimensions
38.659,155.296 to 138.481,155.379 on M2 Board Dimensions
75.489,58.257 to 39.929,156.566 on M2 Board Dimensions
75.489,58.257 to 39.929,156.566 on M2 Board Dimensions
17.577,29.807 to 42.977,29.807 on M2 Board Dimensions
46.172,141.072 to 129.697,141.326 on M2 Board Dimensions
46.055,141.356 to 130.383,141.61 on M2 Board Dimensions
60.533,141.864 to 115.113,141.727 on M2 Board Dimensions
60.533,141.864 to 115.397,141.61 on M2 Board Dimensions
75.997,72.492 to 99.365,72.492 on M2 Board Dimensions
99.365,97.13 to 99.365,72.492 on M2 Board Dimensions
